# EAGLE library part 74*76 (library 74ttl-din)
Dual J-K FLIP FLOP, preset and clear
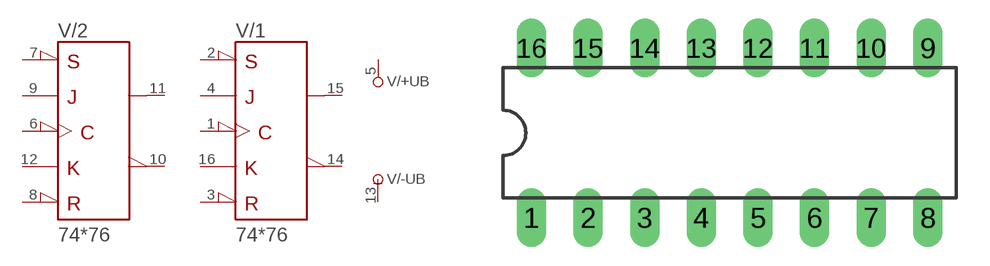
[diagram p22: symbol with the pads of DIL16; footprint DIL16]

Designator prefix V; gates /+UB=+UB /-UB=-UB /1=76 /2=76

## 7476N  [DIL16]
1  /1:CLK  in
2  /1:PRE\  in
3  /1:CLR\  in
4  /1:J  in
5  /+UB:+UB  pwr
6  /2:CLK  in
7  /2:PRE\  in
8  /2:CLR\  in
9  /2:J  in
10  /2:Q\  out
11  /2:Q  out
12  /2:K  in
13  /-UB:-UB  pwr
14  /1:Q\  out
15  /1:Q  out
16  /1:K  in

## Footprint DIL16 (pad centres in mm)
Dual In Line Package
drill 0.813 long: 1 -8.89,-3.81; 2 -6.35,-3.81; 3 -3.81,-3.81; 4 -1.27,-3.81; 5 1.27,-3.81; 6 3.81,-3.81; 7 6.35,-3.81; 8 8.89,-3.81; 9 8.89,3.81; 10 6.35,3.81; 11 3.81,3.81; 12 1.27,3.81; 13 -1.27,3.81; 14 -3.81,3.81; 15 -6.35,3.81; 16 -8.89,3.81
